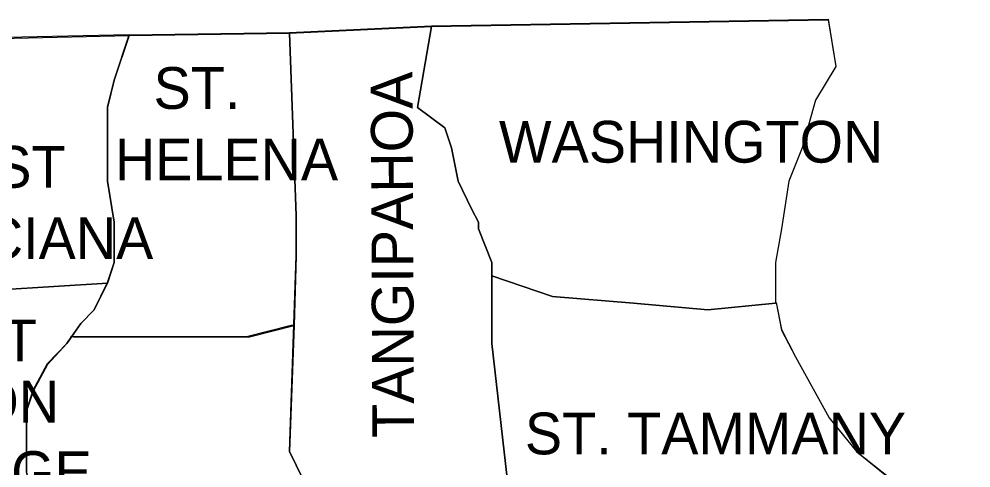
# Model space of a CAD drawing. Extents: x 0.19 to 2.82, y 0.04 to 1.79.
# Drawn here: x 2.4368 to 2.5436, y 1.5325 to 1.5827 of the extents above; entities that cross this region are included whole.
import ezdxf

# ---------------------------------------------------------------- set-up
doc = ezdxf.new("R2010")
doc.units = 0
for name, color, linetype in [('Dist61', 7, 'Continuous'), ('Dist62', 7, 'Continuous'), ('Standard Info', 7, 'Continuous')]:
    doc.layers.add(name, color=color, linetype=linetype)

msp = doc.modelspace()

# ---------------------------------------------------------------- linework, layer by layer
at = {"layer": 'Dist61'}
for points in [[(2.44915, 1.581), (2.42332, 1.58042)], [(2.44674, 1.55325), (2.44749, 1.5555), (2.44749, 1.56008), (2.44674, 1.56458), (2.44674, 1.56983), (2.44674, 1.57292), (2.44749, 1.57592), (2.44915, 1.581)], [(2.44524, 1.5215), (2.44299, 1.52375), (2.43999, 1.526), (2.4384, 1.529), (2.43765, 1.53208), (2.43765, 1.53508), (2.43765, 1.53892), (2.4384, 1.54117), (2.43999, 1.54417), (2.44215, 1.54642), (2.44374, 1.54867), (2.44524, 1.55017), (2.44674, 1.55325)]]:
    msp.add_lwpolyline(points, dxfattribs=at)
at = {"layer": 'Dist62'}
for p, q in [((2.48307, 1.582), (2.52757, 1.58275)), ((2.44915, 1.581), (2.46715, 1.58125)), ((2.46715, 1.58125), (2.48307, 1.582))]:
    msp.add_line(p, q, dxfattribs=at)
for points in [[(2.52757, 1.58275), (2.5284, 1.57742), (2.52615, 1.57367), (2.52465, 1.56833), (2.52315, 1.56458), (2.52232, 1.55925), (2.52165, 1.5555), (2.52165, 1.551)], [(2.44674, 1.55325), (2.44749, 1.5555), (2.44749, 1.56008), (2.44674, 1.56458), (2.44674, 1.56983), (2.44674, 1.57292), (2.44749, 1.57592), (2.44915, 1.581)], [(2.44524, 1.5215), (2.44299, 1.52375), (2.43999, 1.526), (2.4384, 1.529), (2.43765, 1.53208), (2.43765, 1.53508), (2.43765, 1.53892), (2.4384, 1.54117), (2.43999, 1.54417), (2.44215, 1.54642), (2.44374, 1.54867), (2.44524, 1.55017), (2.44674, 1.55325)], [(2.52174, 1.551), (2.52232, 1.548), (2.5239, 1.54492), (2.52765, 1.53808), (2.53074, 1.53433), (2.53449, 1.53133), (2.53749, 1.52525), (2.53824, 1.523), (2.53824, 1.5215), (2.53974, 1.51692), (2.54049, 1.51467), (2.54199, 1.51317), (2.54357, 1.51167), (2.53949, 1.50708)]]:
    msp.add_lwpolyline(points, dxfattribs=at)
at = {"layer": 'Standard Info'}
for p, q in [((2.48307, 1.58192), (2.52757, 1.58267)), ((2.46715, 1.58117), (2.48307, 1.58192)), ((2.44915, 1.58092), (2.46715, 1.58117)), ((2.52165, 1.55092), (2.52174, 1.551)), ((2.46765, 1.54842), (2.46732, 1.54842))]:
    msp.add_line(p, q, dxfattribs=at)
for points in [[(2.52757, 1.58267), (2.5284, 1.57742), (2.52615, 1.57367), (2.52465, 1.56833), (2.52315, 1.56458), (2.52232, 1.55925), (2.52165, 1.5555), (2.52165, 1.55092)], [(2.48307, 1.58192), (2.48149, 1.57283), (2.48457, 1.57058), (2.48532, 1.56833), (2.48607, 1.56458), (2.48757, 1.5615), (2.48832, 1.56), (2.48832, 1.55925), (2.48982, 1.5555), (2.48982, 1.54642), (2.49207, 1.52675)], [(2.48982, 1.554), (2.48982, 1.5555), (2.48832, 1.55925), (2.48832, 1.56), (2.48757, 1.5615), (2.48607, 1.56458), (2.48532, 1.56833), (2.48457, 1.57058), (2.48149, 1.57283), (2.48307, 1.58192)], [(2.42332, 1.58033), (2.44915, 1.58092)], [(2.44915, 1.58092), (2.44749, 1.57592), (2.44674, 1.57283), (2.44674, 1.56983), (2.44674, 1.56458), (2.44749, 1.56), (2.44749, 1.5555), (2.44674, 1.55317)], [(2.44674, 1.55317), (2.44749, 1.5555), (2.44749, 1.56), (2.44674, 1.56458), (2.44674, 1.56983), (2.44674, 1.57283), (2.44749, 1.57592), (2.44915, 1.58092)], [(2.46715, 1.58117), (2.4679, 1.56075), (2.4679, 1.55625), (2.46765, 1.54842)], [(2.47324, 1.52442), (2.47324, 1.52442), (2.47174, 1.52675), (2.47024, 1.529), (2.46865, 1.53125), (2.46715, 1.53433), (2.4679, 1.55625), (2.4679, 1.56075), (2.46715, 1.58117)], [(2.52165, 1.55092), (2.51407, 1.55017), (2.50574, 1.55092), (2.49665, 1.55167), (2.48982, 1.554)], [(2.49207, 1.52675), (2.48982, 1.54642), (2.48982, 1.554)], [(2.48982, 1.554), (2.49665, 1.55167), (2.50574, 1.55092), (2.51407, 1.55017), (2.52165, 1.55092)], [(2.4119, 1.54717), (2.41499, 1.54717), (2.41424, 1.55017), (2.41574, 1.55017), (2.41574, 1.55167), (2.42332, 1.55167), (2.43465, 1.55242), (2.44674, 1.55317)], [(2.44674, 1.55317), (2.43465, 1.55242), (2.42332, 1.55167), (2.41574, 1.55167), (2.41574, 1.55017), (2.41424, 1.55017), (2.41499, 1.54717), (2.41274, 1.54717)], [(2.44674, 1.55317), (2.44524, 1.55017), (2.44374, 1.54867), (2.44215, 1.54642), (2.43999, 1.54408), (2.4384, 1.54108), (2.43765, 1.53883), (2.43765, 1.535), (2.43765, 1.532), (2.4384, 1.529), (2.43999, 1.526), (2.44299, 1.52375), (2.44524, 1.52142)], [(2.44274, 1.54717), (2.44374, 1.54867), (2.44524, 1.55017), (2.44674, 1.55317)], [(2.52174, 1.551), (2.52232, 1.54792), (2.5239, 1.54492), (2.52765, 1.53808), (2.53074, 1.53433), (2.53449, 1.53125), (2.53749, 1.52525), (2.53824, 1.52292), (2.53824, 1.52142), (2.53974, 1.51692), (2.54049, 1.51467), (2.54199, 1.51317), (2.54357, 1.51158), (2.53949, 1.50708)], [(2.46732, 1.54842), (2.46232, 1.54717), (2.44257, 1.54717)], [(2.4429, 1.54717), (2.46265, 1.54717), (2.46765, 1.54842)], [(2.4429, 1.54717), (2.46265, 1.54717), (2.46765, 1.54842)], [(2.46765, 1.54842), (2.46715, 1.53433), (2.46865, 1.53125), (2.47024, 1.529), (2.47174, 1.52675), (2.47324, 1.52442)], [(2.46265, 1.51233), (2.46115, 1.51083), (2.45957, 1.50783), (2.45882, 1.50858), (2.45732, 1.51008), (2.45582, 1.51233), (2.45207, 1.51617), (2.44899, 1.51842), (2.44524, 1.52142), (2.44299, 1.52375), (2.43999, 1.526), (2.4384, 1.529), (2.43765, 1.532), (2.43765, 1.535), (2.43765, 1.53883), (2.4384, 1.54108), (2.43999, 1.54408), (2.44215, 1.54642), (2.44274, 1.54725)]]:
    msp.add_lwpolyline(points, dxfattribs=at)

# ---------------------------------------------------------------- texts
for s, p in [('ST.', (2.45189, 1.57269)), ('WASHINGTON', (2.49063, 1.56667)), ('EAST', (2.42568, 1.56386)), ('HELENA', (2.44756, 1.56469)), ('FELICIANA', (2.41953, 1.55586)), ('EAST', (2.42249, 1.54442)), ('BATON', (2.41974, 1.53756)), ('ST. TAMMANY', (2.49354, 1.534)), ('ROUGE', (2.42202, 1.52967))]:
    msp.add_text(s, height=0.004679, dxfattribs=at).set_placement(p)
msp.add_text('TANGIPAHOA', height=0.004679, rotation=90.2537, dxfattribs=at).set_placement((2.48111, 1.53585))

doc.saveas('drawing.dxf')
